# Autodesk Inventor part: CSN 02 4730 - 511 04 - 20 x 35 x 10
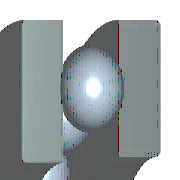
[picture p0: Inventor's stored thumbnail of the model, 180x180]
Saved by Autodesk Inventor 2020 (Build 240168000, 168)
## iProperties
Created: 2019-01
Part Number: CSN 02 4730 - 511 04 - 20 x 35 x 10
Material: Ocel, měkká
Description: Axiální kuličková ložiska jedno- a obousměrná
Document SubType Name: Modeling
Standard: CSN 02 4730
Designer: doma
Standards Organization: CSN
Language: cs-CZ
Size Designation: 511 04 - 20 x 35 x 10
Categories: <MemberInstance><Categories><Category DisplayName="Součásti hřídele" InternalName="7f7aeb1f-a693-4053-b835-cee3144e0d98" Mnemonic="SHFT"><Category DisplayName="
Density: 7.85 g/cm^3
Appearance: Pololeštěná
IsCustomPart: 0
Author: doma
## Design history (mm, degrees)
sketch "Náčrt1" dims "d3" = 4.4 (= 0.44 x KB)
  geometry: L1 (5, 11.8)-(5, 16.2); L2 (7.2, 14)-(2.8, 14); L3 (3, 17.5)-(0, 17.5); L4 (3, 10)-(0, 10); L5 (7, 14.917)-(7, 17.5); L6 (7, 17.5)-(10, 17.5); L7 (10, 17.5)-(10, 10.5); L8 (10, 10.5)-(7, 10.5); L9 (7, 10.5)-(7, 13.083); L10 (3, 17.5)-(3, 14.917); L11 (3, 13.083)-(3, 10); L12 (-1.8, 0)-(10.8, 0) reference; L13 (0, -0.022)-(0, 5.522) reference; 1 further point
  constraints: 22 end point, 5 perpendicular, 2 equal length, 2 midpoint, 2 parallel, 2 point on line, 1 collinear, 10 other
  dimensions: "d8" = 4 diameter of L11 L1 (= 0.4 x KB); "d11" = 20 diameter of L4 L12 (= WD); "d12" = 21 diameter of L8 L12 (= KAD1); "d13" = 35 diameter of L3 L12 (= KID1); "d14" = 35 diameter of L6 L12 (= BD); "d15" = 28 diameter of point (5, 14) L12 (= 0.5 x KID1 + 0.5 x KAD1); "d16" = 5 distance from line of point (5, 14) L13 (= 0.5 x KB); "d18" = 10 distance between parallel lines of L7 L13 (= KB)
revolve "Těleso" stored, may be unused: angle "d9" = 90 deg
revolve "Kulička" stored, may be unused: angle "d10" = 90 deg
pattern_circular "Kuličky" dims angle "d2" = 360 deg
body "Solid1"
fillet "Zaoblení1" dims "d4" = 0.3 (= KRS)
fillet "Zaoblení2" dims "d5" = 0.3 (= KRS)
other parameters: "WD" = 20 [user parameter; used in 2 equation terms], "KAD1" = 21 [user parameter; used in 3 equation terms], "KID1" = 35 [user parameter; used in 3 equation terms], "BD" = 35 [user parameter; used in 2 equation terms], "KB" = 10 [user parameter; used in 6 equation terms], "KRS" = 0.3 [user parameter; used in 2 equation terms], "d0" = 2 (= 0.2 x KB), "d6" = 0, "d7" = 0, "d19" = 0, "d41" = 0, "d42" = 0, "BC" = 1.27e+07 [user parameter], "BBA" = 90 deg [user parameter], "BC0" = 2.28e+07 [user parameter], "BR" = 17.5 (= 0.5 x BD) [user parameter]
